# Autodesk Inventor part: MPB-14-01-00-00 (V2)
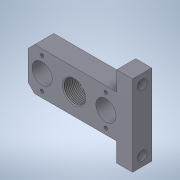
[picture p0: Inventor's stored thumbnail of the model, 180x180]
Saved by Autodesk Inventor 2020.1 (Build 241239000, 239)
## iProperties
Created: 2020-04
Part Number: MPB-14-01-00-00 (V2)
Material: Al 6061
Document SubType Name: Modeling
Designer: Safarabadi
Density: 2.7 g/cm^3
Appearance: Aluminum - Flat
Author: Safarabadi
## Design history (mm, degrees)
derived "MPB-14-01-00-00.ipt"
feature "Solid1::MPB-14-01-00-00.ipt" dims "d0" = 10
tag "TaggingFeature1"
body "Solid1"
